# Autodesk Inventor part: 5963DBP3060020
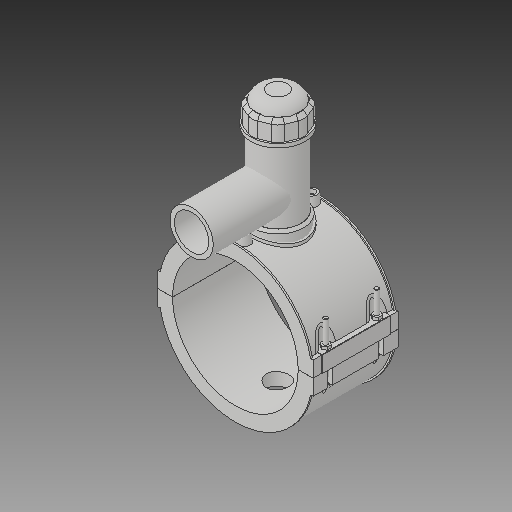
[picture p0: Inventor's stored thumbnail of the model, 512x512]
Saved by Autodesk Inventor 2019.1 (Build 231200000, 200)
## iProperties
Created: 2017-07
Part Number: 5963DBP3060020
Material: Generic
Description: PLASSON TAPPING SADDLE 6''DIPS x 2''IPS
Document SubType Name: Modeling
Designer: KIM
Density: 1 g/cm^3
Appearance: Default
Author: KIM
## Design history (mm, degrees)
derived "5963DBP_5963BUP.ipt"
feature "Solid1::5963DBP_5963BUP.ipt"
feature "Solid2::5963DBP_5963BUP.ipt"
feature "Solid3::5963DBP_5963BUP.ipt"
tag "TaggingFeature1"
body "Solid1"
body "Solid2"
body "Solid3"
other parameters: "d0" = 174.5, "d2" = 215.9, "d3" = 43.625, "d4" = 118.11, "d5" = 0, "d6" = 0.1, "d8" = 0, "d19" = 6, "d20" = 6, "d21" = 70.866, "d23" = 0, "d24" = 35.433, "d26" = 0, "d27" = 3, "d28" = 3, "d29" = 3, "d30" = 58.16667, "d31" = 6, "d32" = 0, "d33" = 0, "d34" = 0.6, "d40" = 108.888, "d41" = 75.035, "d43" = 0, "d45" = 0, "d47" = 175.566, "d70" = 15, "d72" = 0, "d73" = 6, "d75" = 5, "d76" = 0, "d77" = 8.725, "d78" = 117.25, "d79" = 15, "d80" = 47.244, "d82" = 5 deg, "d84" = 4, "d85" = 14, "d86" = 0, "d87" = 3, "d88" = 0, "d89" = 1, "d90" = 1, "d91" = 94.488, "d92" = 0, "d93" = 0.5, "d94" = 91.84211, "d96" = 213.588, "d97" = 2.3622, "d98" = 0, "d120" = 140 deg, "d121" = 24.228, "d122" = 20 deg, "d123" = 418.8, "d124" = 125.64, "d126" = 0, "d143" = 179.735, "d145" = 26.84615, "d149" = 2.6175, "d150" = 29.53077, "d153" = 118.11, "d154" = 0, "d156" = 104.7, "d157" = 160 deg, "d159" = 6.98, "d161" = 2.6175, "d162" = 70.866, "d163" = 0, "d164" = 87.25, "d167" = 17.45, "d168" = 102.14634, "d170" = 3.4335, "d172" = 0, "d173" = 1, "d175" = 87.25, "d176" = 20 deg, "d177" = 12.215, "d178" = 34.9, "d180" = 0, "d183" = 13.96, "d184" = 9.772, "d185" = 38.38575, "d186" = 38.38575, "d187" = 104.7, "d188" = 10.47, "d189" = 12.215, "d190" = 0, "d191" = 157.05, "d193" = 7.3248, "d194" = 4.13385, "d195" = 90 deg, "d197" = 0, "d199" = 0, "d200" = 17.45, "d202" = 0, "d203" = 177.038, "d204" = 71.28325, "d205" = 52.5245, "d206" = 63.77975, "d207" = 132.7785, "d208" = 138.08964, "d209" = 164.64534, "d210" = 64.5301, "d211" = 75.035, "d212" = 60.028, "d213" = 31.4766, "d216" = 0, "d217" = 17.45, "d218" = 17.45, "d219" = 3.49, "d222" = 174.5, "d224" = 0, "d225" = 65.024, "d226" = 60.1, "d227" = 48.08, "d228" = 119.888, "d230" = 5.235, "d_" = 174.5, "B_" = 215.9, "L_" = 118.11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
